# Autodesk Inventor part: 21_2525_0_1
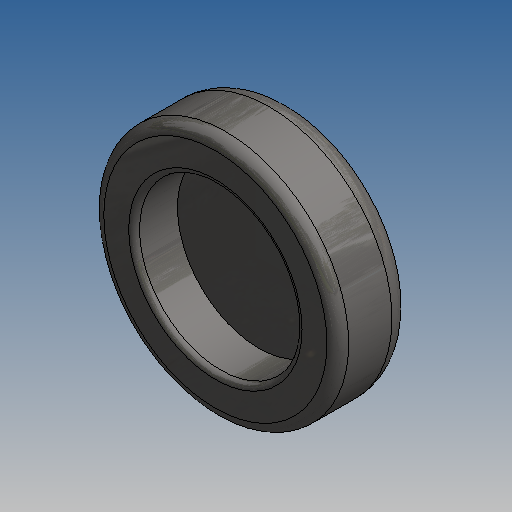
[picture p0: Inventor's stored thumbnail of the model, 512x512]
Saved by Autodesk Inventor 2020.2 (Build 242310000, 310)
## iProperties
Part Number: 21_2525_0_1
Material: Generic
Document SubType Name: Modeling
Designer: amoles
Appearance: Default
Mass: 2.08589 g
Surface Area: 14.5817 cm^2
Volume: 2.08589 cm^3
Density: 1 g/cm^3
Author: amoles
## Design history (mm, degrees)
feature "Base1"
body "Solid1"
